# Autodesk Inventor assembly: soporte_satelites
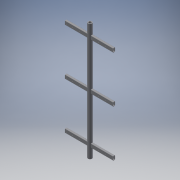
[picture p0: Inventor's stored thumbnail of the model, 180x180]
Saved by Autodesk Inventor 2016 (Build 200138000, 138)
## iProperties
Created: 2016-10
Part Number: soporte_satelites
Document SubType Name: Assembly
Designer: Ingenieria
Author: Ingenieria
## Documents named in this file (3)
- C:\Users\ingenieria\Desktop\INGENIERIA\Proyectos\2016\Enfriador_4\Planos\soporte_satelites.iam
- C:\Users\ingenieria\Desktop\INGENIERIA\Proyectos\2016\Enfriador_4\Planos\Eje_principal.ipt
- C:\Users\ingenieria\Desktop\INGENIERIA\Proyectos\2016\Enfriador_4\Planos\brazo_superior.ipt
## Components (7 placed, 2 different names)
1. Eje_principal:1 — Mate:1, Mate:2, Mate:3, Mate:4, Flush:1, Mate:6, Mate:8, Mate:11, Mate:13, Mate:16
2. brazo_superior:1 — Mate:4, Mate:5, Flush:1, Flush:2, Mate:10
3. brazo_superior:2 — Mate:6, Mate:7, Flush:2
4. brazo_superior:3 — Mate:8, Mate:9, Mate:10, Flush:3, Mate:15
5. brazo_superior:4 — Mate:11, Mate:12, Flush:3
6. brazo_superior:5 — Mate:13, Mate:14, Mate:15, Flush:4
7. brazo_superior:6 — Mate:16, Mate:17, Flush:4
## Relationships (21: Mate 17, Flush 4)
- Mate:1: Eje_principal:1
- Mate:2: Eje_principal:1
- Mate:3: Eje_principal:1
- Mate:4: Eje_principal:1 ↔ brazo_superior:1
- Mate:5: brazo_superior:1
- Flush:1: Eje_principal:1 ↔ brazo_superior:1
- Mate:6: Eje_principal:1 ↔ brazo_superior:2
- Mate:7: brazo_superior:2
- Flush:2: brazo_superior:1 ↔ brazo_superior:2
- Mate:8: Eje_principal:1 ↔ brazo_superior:3
- Mate:9: brazo_superior:3
- Mate:10: brazo_superior:1 ↔ brazo_superior:3
- Mate:11: Eje_principal:1 ↔ brazo_superior:4
- Mate:12: brazo_superior:4
- Flush:3: brazo_superior:3 ↔ brazo_superior:4
- Mate:13: Eje_principal:1 ↔ brazo_superior:5
- Mate:14: brazo_superior:5
- Mate:15: brazo_superior:3 ↔ brazo_superior:5
- Mate:16: Eje_principal:1 ↔ brazo_superior:6
- Mate:17: brazo_superior:6
- Flush:4: brazo_superior:5 ↔ brazo_superior:6
